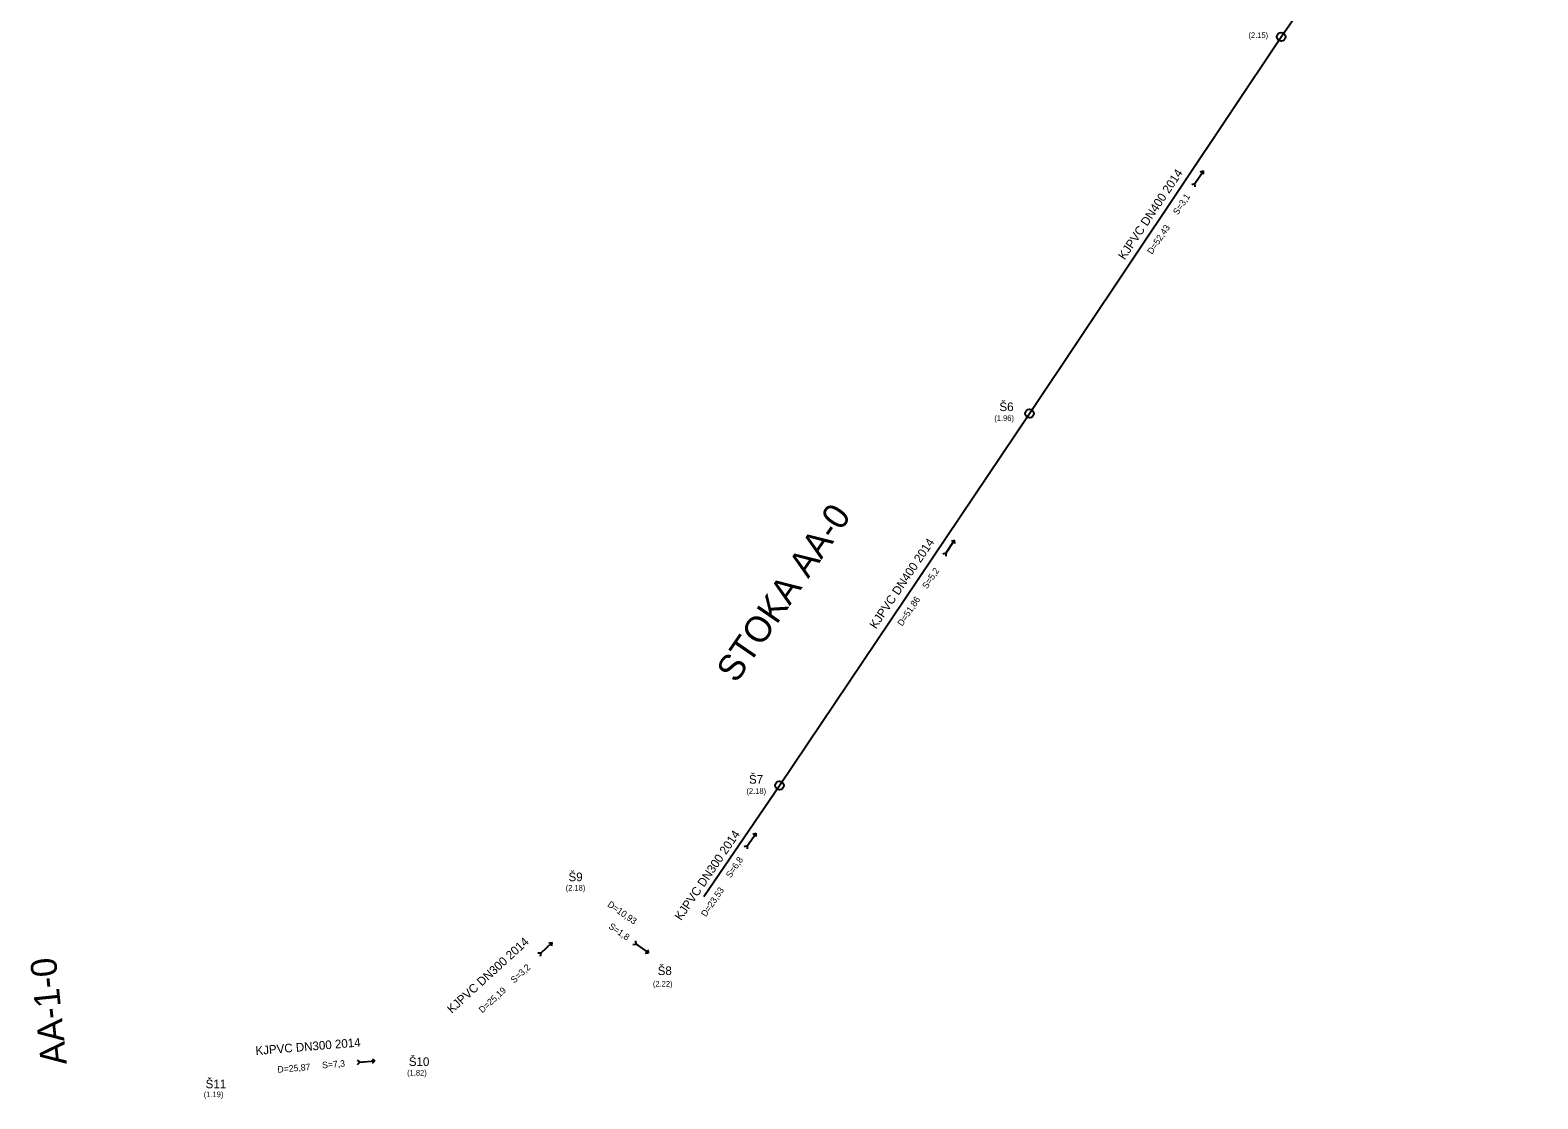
# Model space of a CAD drawing. Extents: x -539706 to -539225, y -1156458 to -1155912.
# Drawn here: x -539462.6 to -539288.2, y -1156224.4 to -1156100.8 of the extents above; entities that cross this region are included whole.
import ezdxf

# ---------------------------------------------------------------- set-up
doc = ezdxf.new("R2010")
doc.units = 0
for name, color, linetype in [('Vrstva 29', 7, 'Continuous'), ('Vrstva 39', 7, 'Continuous'), ('Vrstva 54', 7, 'Continuous'), ('Vrstva 56', 7, 'Continuous'), ('Vrstva 57', 7, 'Continuous'), ('Vrstva 60', 7, 'Continuous'), ('Vrstva 7', 7, 'Continuous'), ('Vrstva 8', 7, 'Continuous')]:
    doc.layers.add(name, color=color, linetype=linetype)

msp = doc.modelspace()

# ---------------------------------------------------------------- linework, layer by layer
at = {"layer": 'Vrstva 29'}
for centre in [(-539317.92, -1156101.55), (-539347.04, -1156145.15), (-539375.97, -1156188.19)]:
    msp.add_circle(centre, 0.5, dxfattribs=at)
at = {"layer": 'Vrstva 39'}
for p, q in [((-539327.897, -1156118.524), (-539326.921, -1156117.067)), ((-539327.286, -1156117.192), (-539326.921, -1156117.067)), ((-539326.9, -1156117.45), (-539326.921, -1156117.067)), ((-539328.268, -1156118.652), (-539327.897, -1156118.524)), ((-539327.872, -1156118.917), (-539327.897, -1156118.524)), ((-539356.689, -1156161.245), (-539355.709, -1156159.791)), ((-539356.074, -1156159.915), (-539355.709, -1156159.791)), ((-539355.689, -1156160.174), (-539355.709, -1156159.791)), ((-539357.061, -1156161.371), (-539356.689, -1156161.245)), ((-539356.665, -1156161.638), (-539356.689, -1156161.245)), ((-539379.663, -1156195.133), (-539378.674, -1156193.684)), ((-539379.04, -1156193.806), (-539378.674, -1156193.684)), ((-539378.657, -1156194.067), (-539378.674, -1156193.684)), ((-539380.035, -1156195.257), (-539379.663, -1156195.133)), ((-539379.641, -1156195.526), (-539379.663, -1156195.133)), ((-539392.656, -1156206.171), (-539392.536, -1156206.544)), ((-539403.922, -1156207.56), (-539403.531, -1156207.525)), ((-539403.601, -1156207.912), (-539403.531, -1156207.525)), ((-539403.531, -1156207.525), (-539402.236, -1156206.342)), ((-539402.62, -1156206.377), (-539402.236, -1156206.342)), ((-539402.307, -1156206.719), (-539402.236, -1156206.342)), ((-539392.929, -1156206.562), (-539392.536, -1156206.544)), ((-539392.536, -1156206.544), (-539391.098, -1156207.549)), ((-539391.481, -1156207.562), (-539391.098, -1156207.549)), ((-539391.216, -1156207.181), (-539391.098, -1156207.549)), ((-539424.826, -1156219.971), (-539424.495, -1156220.182)), ((-539424.788, -1156220.446), (-539424.495, -1156220.182)), ((-539424.495, -1156220.182), (-539422.747, -1156220.041)), ((-539423.072, -1156219.832), (-539422.747, -1156220.041)), ((-539423.034, -1156220.295), (-539422.747, -1156220.041))]:
    msp.add_line(p, q, dxfattribs=at)
at = {"layer": 'Vrstva 8'}
for p, q in [((-539317.92, -1156101.55), (-539288.24, -1156058.36)), ((-539347.04, -1156145.15), (-539317.92, -1156101.55)), ((-539375.97, -1156188.19), (-539347.04, -1156145.15)), ((-539384.701, -1156201.016), (-539375.97, -1156188.19))]:
    msp.add_line(p, q, dxfattribs=at)

# ---------------------------------------------------------------- texts
at = {"layer": 'Vrstva 54'}
for s, rotation, p in [('S=3,1', 56.26143, (-539329.883, -1156122.231)), ('D=52,43', 56.26144, (-539332.866, -1156126.785)), ('S=5,2', 56.09241, (-539358.9, -1156165.51)), ('D=51,86', 56.09237, (-539361.761, -1156169.81)), ('S=6,8', 55.75608, (-539381.604, -1156198.948)), ('D=23,53', 55.7561, (-539384.474, -1156203.438)), ('D=10,93', 325.13249, (-539395.928, -1156202.106)), ('S=1,8', 325.13247, (-539395.8, -1156204.64)), ('S=3,2', 42.44202, (-539406.651, -1156211.105)), ('D=25,19', 42.44199, (-539410.327, -1156214.56)), ('S=7,3', 4.70106, (-539428.834, -1156220.91)), ('D=25,87', 4.7011, (-539434.002, -1156221.417))]:
    msp.add_text(s, height=0.75, rotation=rotation, dxfattribs=at).set_placement(p)
at = {"layer": 'Vrstva 56'}
for s, p in [('(2.15)', (-539321.71, -1156101.701)), ('(1.96)', (-539351.109, -1156146.003)), ('(2.18)', (-539379.78, -1156189.15)), ('(2.18)', (-539400.686, -1156200.341)), ('(2.22)', (-539390.6, -1156211.45)), ('(1.82)', (-539419.033, -1156221.744)), ('(1.19)', (-539442.555, -1156224.24))]:
    msp.add_text(s, height=0.65, dxfattribs=at).set_placement(p)
at = {"layer": 'Vrstva 57'}
for s, p in [('Š6', (-539350.519, -1156144.863)), ('Š7', (-539379.49, -1156187.97)), ('Š9', (-539400.363, -1156199.253)), ('Š8', (-539390.05, -1156210.11)), ('Š10', (-539418.836, -1156220.631)), ('Š11', (-539442.336, -1156223.209))]:
    msp.add_text(s, height=1, dxfattribs=at).set_placement(p)
at = {"layer": 'Vrstva 60'}
for s, rotation, p in [('STOKA AA-0', 55.51677, (-539380.966, -1156176.441)), ('AA-1-0', 95.87066, (-539458.392, -1156220.391))]:
    msp.add_text(s, height=3, rotation=rotation, dxfattribs=at).set_placement(p)
at = {"layer": 'Vrstva 7'}
for s, rotation, p in [('KJPVC DN400 2014', 56.26143, (-539336.03, -1156127.435)), ('KJPVC DN400 2014', 56.09241, (-539364.799, -1156170.138)), ('KJPVC DN300 2014', 55.75608, (-539387.335, -1156203.879)), ('KJPVC DN300 2014', 42.44202, (-539413.857, -1156214.615)), ('KJPVC DN300 2014', 4.70106, (-539436.528, -1156219.371))]:
    msp.add_text(s, height=1, rotation=rotation, dxfattribs=at).set_placement(p)

doc.saveas('drawing.dxf')
